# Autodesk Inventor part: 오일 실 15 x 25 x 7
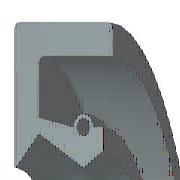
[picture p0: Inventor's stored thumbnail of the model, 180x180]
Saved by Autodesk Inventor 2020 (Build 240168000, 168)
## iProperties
Created: 2012-02
Part Number: 오일 실 15 x 25 x 7
Material: 고무
Description: 오일-실
Document SubType Name: Modeling
Standard: KS B 2804
Designer: mduedu
Standards Organization: KS
Language: ko-KR
Size Designation: D - 15 25 7
Categories: <MemberInstance><Categories><Category DisplayName="샤프트 부품" InternalName="7f7aeb1f-a693-4053-b835-cee3144e0d98" Mnemonic="SHFT"><Category DisplayName="실링" Intern
Density: 0.93 g/cm^3
Mass: 1.46464 g
Surface Area: 21.6685 cm^2
Volume: 1.57488 cm^3
Appearance: 고무 - 검은색 - 버전 1.1
IsCustomPart: 1
Author: mduedu
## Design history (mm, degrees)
revolve "본체" stored, may be unused: angle "d17" = 90 deg
revolve "스프링1" stored, may be unused: angle "d18" = 90 deg
body "Solid1"
sketch "스케치1"
  geometry: L1 (0, 12.5)-(7, 12.5); L2 (7, 10.75)-(1.75, 10.75); L3 (1.75, 9.25)-(4.9, 7.5); L4 (4.9, 7.5)-(0, 7.5); L5 (0, 0)-(9.586, 0) reference; L6 (4.9, 7.5)-(6.3, 8.375); L7 (0, 18)-(0, -3) reference; L8 (-1.941, 0)-(11.507, 0) reference; L9 (4.2, 9.6)-(1.75, 10.09); L10 (1.75, 10.09)-(1.75, 10.75); L11 (0, 12.5)-(0, 7.588); L12 (4.9, 7.5)-(0, 7.5); L13 (1.75, 9.25)-(0.152, 7.528); L14 (7, 12.5)-(7, 10.75); L15 (5.6, 9.6)-(6.3, 9.6); L16 (6.3, 9.6)-(6.3, 8.375); C1 r 0.455 at (4.9, 9.6); A1 r 0.7 centre (4.9, 9.6) between (5.6, 9.6) and (4.2, 9.6); A2 r 0.088 centre (0.088, 7.588) between (0, 7.588) and (0.152, 7.528); 1 further point
  constraints: 28 end point, 5 horizontal alignment, 5 point on line, 4 point on circle, 4 vertical alignment, 3 centre point, 3 tangent, 2 collinear, 2 horizontal, 2 perpendicular, 1 coincident, 1 parallel
  dimensions: "d0" = 25 diameter of L1 L5 (= SD2); "d1" = 1.75 distance of L1.end L2.start (= SD); "d2" = 0.91 diameter of C1 (= SPDI); "d3" = 1.4 diameter of A1 (= SPDA); "d4" = 15 diameter of L3.end L5 (= NND); "d5" = 18.5 diameter of L3.start L5 (= TKDM); "d7" = 20.18 diameter of L9.end L5 (= TKDM + 0.24 x SWDT); "d8" = 1.75 distance between parallel lines of L11 L10 (= SD); "d9" = 4.9 distance from line of L11 C1.centre (= SPDST); "d10" = 19.2 diameter of C1.centre L5 (= HLDM); "d11" = 0.0875 radius of A2 (= 0.25 x LAB); "d12" = 6.3 distance between parallel lines of L11 L16 (= SDI); "d13" = 16.75 diameter of L6.end L5 (= ABDM); "d14" = 7 distance from line of L11 L1.end (= SWDT)
fillet "모깎기1" dims "d6" = 0.3 (= RR)
other parameters: "SD2" = 25 [user parameter; used in 1 equation term], "SWDT" = 7 [user parameter; used in 2 equation terms], "RR" = 0.3 [user parameter; used in 1 equation term], "SD" = 1.75 [user parameter; used in 2 equation terms], "NND" = 15 [user parameter; used in 1 equation term], "SPDA" = 1.4 [user parameter; used in 1 equation term], "SPDI" = 0.91 [user parameter; used in 1 equation term], "TKDM" = 18.5 [user parameter; used in 2 equation terms], "HLDM" = 19.2 [user parameter; used in 1 equation term], "ABDM" = 16.75 [user parameter; used in 1 equation term], "SDI" = 6.3 [user parameter; used in 1 equation term], "SPDST" = 4.9 [user parameter; used in 1 equation term], "LAB" = 0.35 [user parameter; used in 1 equation term], "d15" = 0, "d16" = 0, "d19" = 0
